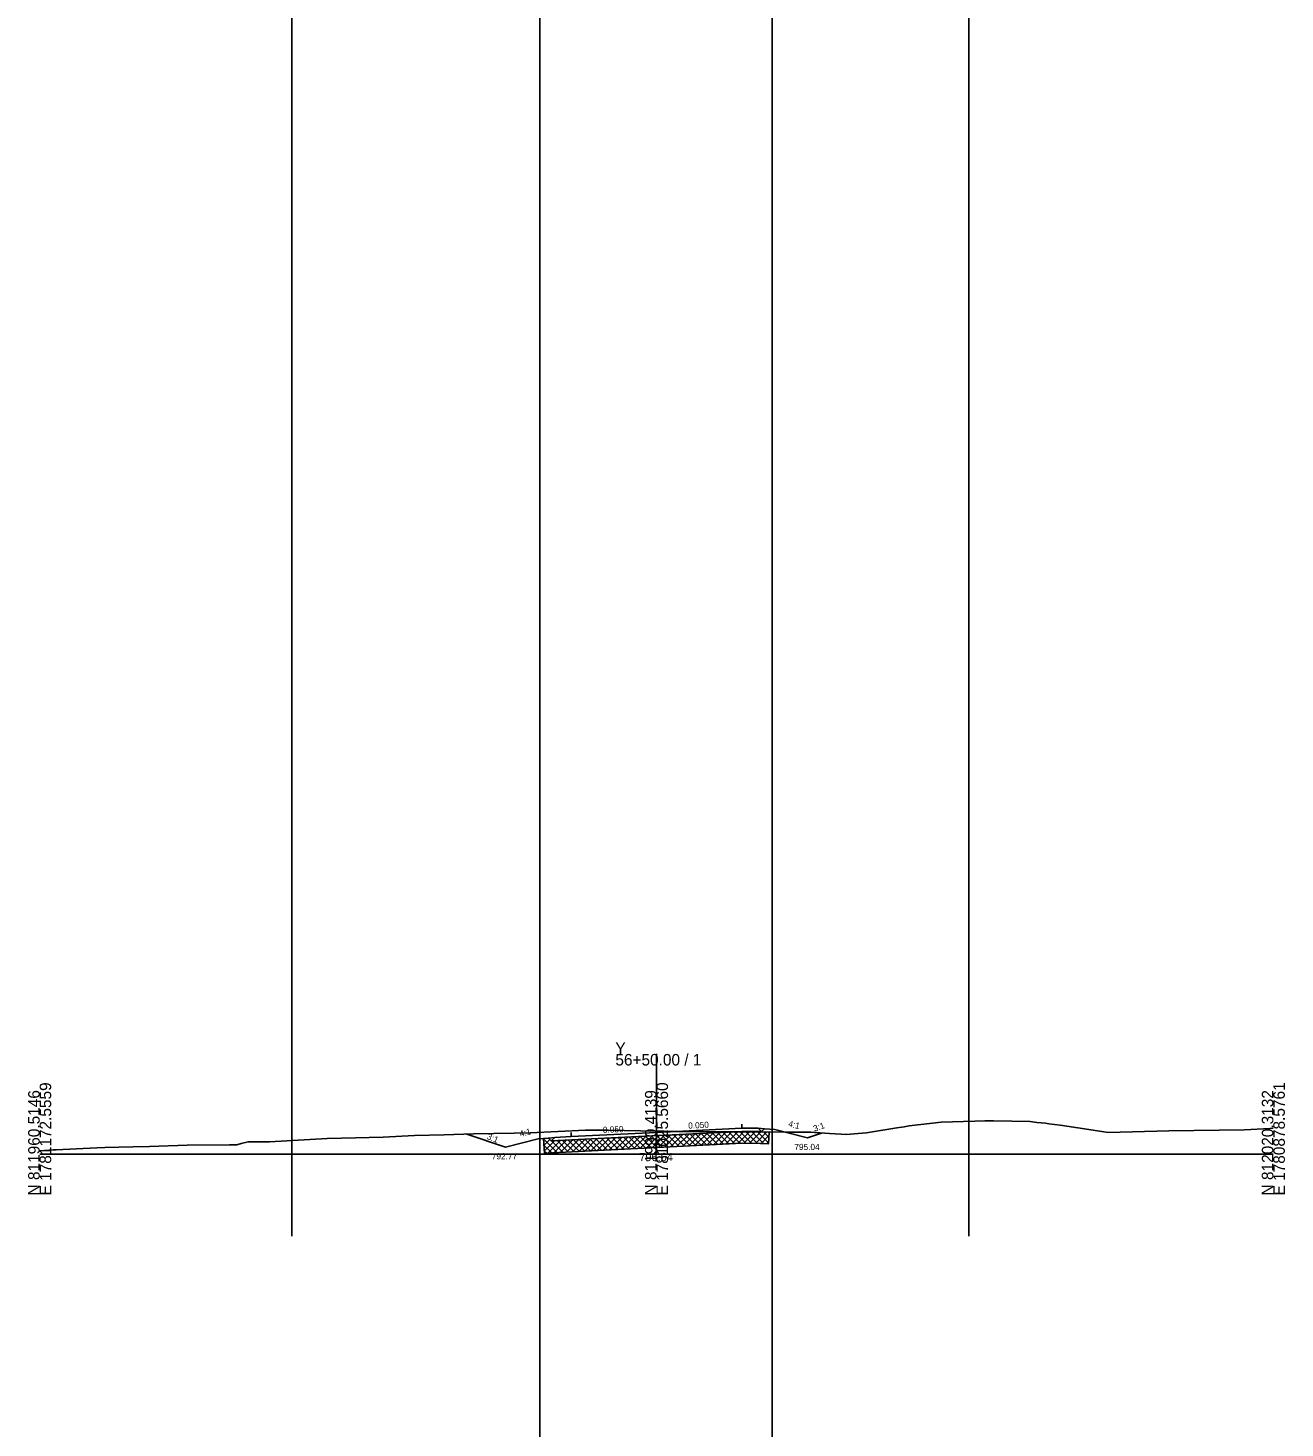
# Model space of a CAD drawing. Extents: x -12583 to 5303, y -44 to 25667.
# Drawn here: x 3997.2 to 4302.8, y 6933.5 to 7273.8 of the extents above; entities that cross this region are included whole.
import ezdxf

# ---------------------------------------------------------------- set-up
doc = ezdxf.new("R2010")
doc.units = 0
for name, color, linetype in [('Exist Cross Section Cell', 7, 'Continuous'), ('Exist XS Center Line Elevation Label', 7, 'Continuous'), ('Exist XS Ground Line', 7, 'Continuous'), ('Prop XS Ditch Slope Text', 7, 'Continuous'), ('Prop XS Ditch Standard Text', 7, 'Continuous'), ('Prop XS Dump Level', 7, 'Continuous'), ('Prop XS Earthwork Shape', 7, 'Continuous'), ('Prop XS Earthwork Undercut', 7, 'Continuous'), ('Prop XS EOT Tick Mark', 7, 'Continuous'), ('Prop XS Exc Vertical Line 1', 7, 'Continuous'), ('Prop XS Exc Vertical Line 2', 7, 'Continuous'), ('Prop XS Finish Grade', 7, 'Continuous'), ('Prop XS Finish Grade Earthwork', 7, 'Continuous'), ('Prop XS Finish Grade Paved Shoulder', 7, 'Continuous'), ('Prop XS Finish Grade Pavement', 7, 'Continuous'), ('Prop XS Pvmt Edge Slope', 7, 'Continuous'), ('Prop XS SE Text', 7, 'Continuous'), ('Prop XS Side Slope Text', 7, 'Continuous'), ('Prop XS Subgrade Earthwork', 7, 'Continuous'), ('Prop XS Undercut Exc Hatch', 7, 'Continuous'), ('Scratch_Level_1', 7, 'Continuous'), ('Scratch_Level_2', 7, 'Continuous'), ('Scratch_Level_3', 7, 'Continuous'), ('Scratch_Level_4', 7, 'Continuous'), ('Scratch_Level_6', 7, 'Continuous')]:
    doc.layers.add(name, color=color, linetype=linetype)

msp = doc.modelspace()

# ---------------------------------------------------------------- linework, layer by layer
at = {"layer": 'Exist Cross Section Cell'}
for p, q in [((4150, 7000), (4150, 7024.39)), ((4000, 7000), (4150, 7000)), ((4150, 7000), (4300, 7000))]:
    msp.add_line(p, q, dxfattribs=at)
at = {"layer": 'Exist XS Ground Line'}
for p, q in [((4211.47, 7006.89), (4219.25, 7007.79)), ((4219.25, 7007.79), (4227.42, 7008.06)), ((4227.42, 7008.06), (4229.86, 7008.13)), ((4229.86, 7008.13), (4231.93, 7008.1)), ((4231.93, 7008.1), (4240.89, 7007.98)), ((4240.89, 7007.98), (4242.49, 7007.75)), ((4083.51, 7004.14), (4091.12, 7004.57)), ((4091.12, 7004.57), (4098.37, 7004.7)), ((4098.37, 7004.7), (4105.5, 7004.94)), ((4105.5, 7004.94), (4115.39, 7005.14)), ((4115.39, 7005.14), (4119.29, 7005.26)), ((4119.29, 7005.26), (4132.74, 7005.86)), ((4132.74, 7005.86), (4134.88, 7005.87)), ((4134.88, 7005.87), (4138.25, 7005.85)), ((4138.25, 7005.85), (4150, 7005.64)), ((4150, 7005.64), (4151.89, 7005.6)), ((4151.89, 7005.6), (4170.92, 7005.45)), ((4170.92, 7005.45), (4172.83, 7005.47)), ((4172.83, 7005.47), (4174.69, 7005.44)), ((4174.69, 7005.44), (4187.56, 7005.36)), ((4187.56, 7005.36), (4192.08, 7005.03)), ((4192.08, 7005.03), (4196.25, 7004.79)), ((4196.25, 7004.79), (4198.05, 7004.98)), ((4198.05, 7004.98), (4201.03, 7005.25)), ((4201.03, 7005.25), (4208.45, 7006.44)), ((4208.45, 7006.44), (4210.21, 7006.71)), ((4210.21, 7006.71), (4211.47, 7006.89)), ((4242.49, 7007.75), (4244.61, 7007.58)), ((4244.61, 7007.58), (4245.41, 7007.39)), ((4245.41, 7007.39), (4248.19, 7007.07)), ((4248.19, 7007.07), (4254.08, 7006.18)), ((4254.08, 7006.18), (4259.86, 7005.32)), ((4259.86, 7005.32), (4274.61, 7005.68)), ((4274.61, 7005.68), (4292.97, 7005.94)), ((4292.97, 7005.94), (4299.16, 7006.29)), ((4299.16, 7006.29), (4300, 7006.33)), ((4000, 7000.81), (4003.29, 7001.05)), ((4003.29, 7001.05), (4004.04, 7001.09)), ((4004.04, 7001.09), (4013.86, 7001.6)), ((4013.86, 7001.6), (4015.85, 7001.66)), ((4015.85, 7001.66), (4022.63, 7001.82)), ((4022.63, 7001.82), (4026.69, 7001.93)), ((4026.69, 7001.93), (4035.83, 7002.26)), ((4035.83, 7002.26), (4046.17, 7002.33)), ((4046.17, 7002.33), (4047.92, 7002.34)), ((4047.92, 7002.34), (4048.96, 7002.64)), ((4048.96, 7002.64), (4050.67, 7003.03)), ((4050.67, 7003.03), (4055.92, 7003.04)), ((4055.92, 7003.04), (4065.67, 7003.57)), ((4065.67, 7003.57), (4069.92, 7003.86)), ((4069.92, 7003.86), (4073.39, 7003.95)), ((4073.39, 7003.95), (4083.51, 7004.14))]:
    msp.add_line(p, q, dxfattribs=at)
at = {"layer": 'Prop XS Dump Level'}
for p, q in [((4129.25, 7004.29), (4150, 7005.32)), ((4150, 7005.32), (4170.75, 7006.36))]:
    msp.add_line(p, q, dxfattribs=at)
at = {"layer": 'Prop XS Earthwork Shape'}
for points in [[(4138.25, 7005.85), (4150, 7005.64), (4151.89, 7005.6), (4168.78, 7005.47), (4147.16, 7004.39), (4129.29, 7003.49), (4124.42, 7003.25), (4123.7, 7003.96), (4121.25, 7003.77), (4113.25, 7001.77), (4103.89, 7004.89), (4105.5, 7004.94), (4115.39, 7005.14), (4119.29, 7005.26), (4132.74, 7005.86), (4134.88, 7005.87)], [(4172.83, 7005.47), (4174.69, 7005.44), (4181.32, 7005.4), (4178.75, 7006.04), (4176.24, 7006.22), (4175.55, 7005.52), (4170.77, 7005.57), (4168.78, 7005.47), (4170.92, 7005.45)], [(4181.32, 7005.4), (4186.75, 7004.04), (4190.14, 7005.17), (4187.56, 7005.36)]]:
    msp.add_lwpolyline(points, close=True, dxfattribs=at)
at = {"layer": 'Prop XS Earthwork Undercut'}
for p, q in [((4177.41, 7005.42), (4177.21, 7002.51)), ((4122.5, 7003.87), (4122.79, 7000.23)), ((4150.15, 7001.66), (4129.4, 7000.62)), ((4170.81, 7002.69), (4150.15, 7001.66)), ((4170.81, 7002.69), (4175.3, 7002.65)), ((4175.3, 7002.65), (4177.21, 7002.51)), ((4124.74, 7000.39), (4122.79, 7000.23)), ((4129.4, 7000.62), (4124.74, 7000.39))]:
    msp.add_line(p, q, dxfattribs=at)
at = {"layer": 'Prop XS EOT Tick Mark'}
for p, q in [((4129.25, 7004.29), (4129.25, 7005.29)), ((4170.75, 7006.36), (4170.75, 7007.36))]:
    msp.add_line(p, q, dxfattribs=at)
at = {"layer": 'Prop XS Exc Vertical Line 1'}
msp.add_line((4121.63, 6478.95), (4121.63, 9656.26), dxfattribs=at)
at = {"layer": 'Prop XS Exc Vertical Line 2'}
msp.add_line((4178.09, 6478.95), (4178.09, 9642.11), dxfattribs=at)
at = {"layer": 'Prop XS Finish Grade'}
for p, q in [((4174.75, 7006.32), (4176.24, 7006.22)), ((4125.25, 7004.09), (4123.7, 7003.96))]:
    msp.add_line(p, q, dxfattribs=at)
at = {"layer": 'Prop XS Finish Grade Earthwork'}
for p, q in [((4113.25, 7001.77), (4103.89, 7004.89)), ((4176.24, 7006.22), (4178.75, 7006.04)), ((4178.75, 7006.04), (4186.75, 7004.04)), ((4186.75, 7004.04), (4190.14, 7005.17)), ((4121.25, 7003.77), (4113.25, 7001.77)), ((4121.25, 7003.77), (4123.7, 7003.96))]:
    msp.add_line(p, q, dxfattribs=at)
at = {"layer": 'Prop XS Finish Grade Paved Shoulder'}
for p, q in [((4170.75, 7006.36), (4174.75, 7006.32)), ((4129.25, 7004.29), (4125.25, 7004.09))]:
    msp.add_line(p, q, dxfattribs=at)
at = {"layer": 'Prop XS Finish Grade Pavement'}
for p, q in [((4129.25, 7004.29), (4150, 7005.32)), ((4150, 7005.32), (4170.75, 7006.36))]:
    msp.add_line(p, q, dxfattribs=at)
at = {"layer": 'Prop XS Pvmt Edge Slope'}
for p, q in [((4174.75, 7006.32), (4175.55, 7005.52)), ((4125.25, 7004.09), (4124.42, 7003.25))]:
    msp.add_line(p, q, dxfattribs=at)
at = {"layer": 'Prop XS Subgrade Earthwork'}
for p, q in [((4129.29, 7003.49), (4147.16, 7004.39)), ((4147.16, 7004.39), (4170.77, 7005.57)), ((4170.77, 7005.57), (4175.55, 7005.52)), ((4175.55, 7005.52), (4176.24, 7006.22)), ((4124.42, 7003.25), (4123.7, 7003.96)), ((4129.29, 7003.49), (4124.42, 7003.25))]:
    msp.add_line(p, q, dxfattribs=at)
at = {"layer": 'Prop XS Undercut Exc Hatch'}
for p, q in [((4144.48, 7001.38), (4147.51, 7004.41)), ((4145.97, 7001.45), (4149, 7004.48)), ((4150, 7001.76), (4147.36, 7004.4)), ((4150, 7003.17), (4148.71, 7004.47)), ((4150, 7002.66), (4151.97, 7004.63)), ((4150, 7004.07), (4150.48, 7004.55)), ((4152.8, 7001.79), (4150.06, 7004.53)), ((4150.43, 7001.67), (4153.46, 7004.7)), ((4154.14, 7001.86), (4151.4, 7004.6)), ((4151.92, 7001.75), (4154.95, 7004.78)), ((4155.49, 7001.93), (4152.75, 7004.67)), ((4153.41, 7001.82), (4156.44, 7004.85)), ((4156.84, 7001.99), (4154.1, 7004.73)), ((4154.9, 7001.9), (4157.93, 7004.93)), ((4158.18, 7002.06), (4155.44, 7004.8)), ((4156.39, 7001.97), (4159.42, 7005)), ((4159.53, 7002.13), (4156.79, 7004.87)), ((4160, 7003.07), (4158.14, 7004.94)), ((4160, 7004.49), (4159.48, 7005)), ((4160, 7002.76), (4162.39, 7005.15)), ((4160, 7004.17), (4160.9, 7005.08)), ((4162.22, 7002.26), (4160, 7004.49)), ((4163.57, 7002.33), (4160.83, 7005.07)), ((4160.85, 7002.2), (4163.88, 7005.22)), ((4164.92, 7002.4), (4162.18, 7005.14)), ((4162.34, 7002.27), (4165.37, 7005.3)), ((4166.27, 7002.47), (4163.52, 7005.21)), ((4163.83, 7002.34), (4166.86, 7005.37)), ((4167.61, 7002.53), (4164.87, 7005.27)), ((4165.32, 7002.42), (4168.35, 7005.45)), ((4168.96, 7002.6), (4166.22, 7005.34)), ((4166.81, 7002.49), (4169.78, 7005.46)), ((4170, 7002.97), (4167.57, 7005.41)), ((4170, 7004.39), (4168.92, 7005.47)), ((4170, 7002.86), (4172.61, 7005.47)), ((4170, 7004.27), (4171.18, 7005.45)), ((4171.7, 7002.68), (4170, 7004.39)), ((4173.13, 7002.67), (4170.35, 7005.46)), ((4171.25, 7002.69), (4174.01, 7005.45)), ((4174.56, 7002.66), (4171.76, 7005.46)), ((4172.65, 7002.67), (4175.41, 7005.44)), ((4176.03, 7002.6), (4173.16, 7005.47)), ((4174.05, 7002.66), (4176.81, 7005.43)), ((4177.23, 7002.81), (4174.6, 7005.44)), ((4175.44, 7002.64), (4177.35, 7004.55)), ((4177.32, 7004.14), (4176.03, 7005.43)), ((4125.86, 7000.45), (4122.51, 7003.8)), ((4124.52, 7000.37), (4122.63, 7002.26)), ((4122.64, 7002.17), (4124.07, 7003.6)), ((4122.74, 7000.86), (4125.18, 7003.29)), ((4123.6, 7000.3), (4126.67, 7003.36)), ((4127.21, 7000.51), (4124.47, 7003.25)), ((4125.12, 7000.41), (4128.15, 7003.44)), ((4128.55, 7000.58), (4125.81, 7003.32)), ((4126.61, 7000.48), (4129.64, 7003.51)), ((4129.9, 7000.65), (4127.16, 7003.39)), ((4128.1, 7000.56), (4130, 7002.46)), ((4130, 7001.96), (4128.51, 7003.46)), ((4129.59, 7000.63), (4130, 7001.04)), ((4130, 7003.38), (4129.85, 7003.52)), ((4130, 7001.04), (4132.62, 7003.66)), ((4130, 7002.46), (4131.13, 7003.59)), ((4132.59, 7000.78), (4130, 7003.38)), ((4131.25, 7000.71), (4130, 7001.96)), ((4131.08, 7000.71), (4134.11, 7003.74)), ((4133.94, 7000.85), (4131.2, 7003.59)), ((4135.29, 7000.92), (4132.55, 7003.66)), ((4132.57, 7000.78), (4135.6, 7003.81)), ((4136.63, 7000.98), (4133.89, 7003.72)), ((4134.06, 7000.86), (4137.09, 7003.88)), ((4137.98, 7001.05), (4135.24, 7003.79)), ((4135.55, 7000.93), (4138.57, 7003.96)), ((4139.33, 7001.12), (4136.59, 7003.86)), ((4137.03, 7001), (4140, 7003.97)), ((4140, 7001.86), (4137.93, 7003.93)), ((4138.52, 7001.08), (4140, 7002.56)), ((4140, 7003.28), (4139.28, 7003.99)), ((4140, 7002.56), (4141.55, 7004.11)), ((4140, 7003.97), (4140.06, 7004.03)), ((4142.02, 7001.25), (4140, 7003.28)), ((4140.67, 7001.19), (4140, 7001.86)), ((4140.01, 7001.15), (4143.04, 7004.18)), ((4143.37, 7001.32), (4140.63, 7004.06)), ((4141.5, 7001.23), (4144.53, 7004.26)), ((4144.72, 7001.39), (4141.97, 7004.13)), ((4142.99, 7001.3), (4146.02, 7004.33)), ((4146.06, 7001.46), (4143.32, 7004.2)), ((4147.41, 7001.52), (4144.67, 7004.26)), ((4148.76, 7001.59), (4146.02, 7004.33)), ((4147.45, 7001.53), (4150, 7004.07)), ((4148.94, 7001.6), (4150, 7002.66)), ((4151.45, 7001.72), (4150, 7003.17)), ((4150.1, 7001.66), (4150, 7001.76)), ((4157.88, 7002.05), (4160, 7004.17)), ((4159.36, 7002.12), (4160, 7002.76)), ((4160.88, 7002.2), (4160, 7003.07)), ((4168.3, 7002.57), (4170, 7004.27)), ((4169.78, 7002.64), (4170, 7002.86)), ((4170.31, 7002.67), (4170, 7002.97)), ((4176.76, 7002.55), (4177.25, 7003.03)), ((4123.21, 7000.27), (4122.75, 7000.72))]:
    msp.add_line(p, q, dxfattribs=at)
at = {"layer": 'Scratch_Level_1'}
msp.add_line((4061.32, 9572.59), (4061.32, 6980.12), dxfattribs=at)
at = {"layer": 'Scratch_Level_2'}
msp.add_line((4225.92, 9572.59), (4225.92, 6980.12), dxfattribs=at)
at = {"layer": 'Scratch_Level_3'}
msp.add_lwpolyline([(4129.25, 7004.29), (4150, 7005.32), (4155.11, 7005.58), (4168.78, 7005.47), (4147.16, 7004.39), (4129.29, 7003.49), (4124.42, 7003.25), (4123.7, 7003.96), (4125.25, 7004.09)], close=True, dxfattribs=at)
at = {"layer": 'Scratch_Level_4'}
for points in [[(4103.89, 7004.89), (4105.5, 7004.94), (4115.39, 7005.14), (4119.29, 7005.26), (4132.74, 7005.86), (4134.88, 7005.87), (4138.25, 7005.85), (4150, 7005.64), (4151.89, 7005.6), (4168.78, 7005.47), (4147.16, 7004.39), (4129.29, 7003.49), (4124.42, 7003.25), (4123.7, 7003.96), (4121.25, 7003.77), (4113.25, 7001.77)], [(4181.32, 7005.4), (4187.56, 7005.36), (4190.14, 7005.17), (4186.75, 7004.04)]]:
    msp.add_lwpolyline(points, close=True, dxfattribs=at)
at = {"layer": 'Scratch_Level_6'}
msp.add_lwpolyline([(4122.5, 7003.87), (4123.7, 7003.96), (4124.42, 7003.25), (4129.29, 7003.49), (4147.16, 7004.39), (4168.78, 7005.47), (4170.92, 7005.45), (4172.83, 7005.47), (4174.69, 7005.44), (4177.41, 7005.42), (4177.21, 7002.51), (4175.3, 7002.65), (4170.81, 7002.69), (4150.15, 7001.66), (4129.4, 7000.62), (4124.74, 7000.39), (4122.79, 7000.23)], close=True, dxfattribs=at)
msp.add_lwpolyline([(4122.5, 7003.87), (4123.7, 7003.96), (4124.42, 7003.25), (4129.29, 7003.49), (4147.16, 7004.39), (4168.78, 7005.47), (4170.92, 7005.45), (4172.83, 7005.47), (4174.69, 7005.44), (4177.41, 7005.42), (4177.21, 7002.51), (4175.3, 7002.65), (4170.81, 7002.69), (4150.15, 7001.66), (4129.4, 7000.62), (4124.74, 7000.39), (4122.79, 7000.23)], close=True, dxfattribs=at)

# ---------------------------------------------------------------- texts
at = {"layer": 'Exist Cross Section Cell'}
for s, p in [('Y', (4140, 7024.39)), ('56+50.00 / 1', (4140, 7021.59))]:
    msp.add_text(s, height=2.8, dxfattribs=at).set_placement(p)
for s, p in [('N 811960.5146', (4000, 6990)), ('E 1781172.5559', (4002.8, 6990)), ('N 811990.4139', (4150, 6990)), ('E 1781025.5660', (4152.8, 6990)), ('N 812020.3132', (4300, 6990)), ('E 1780878.5761', (4302.8, 6990))]:
    msp.add_text(s, height=2.8, rotation=90, dxfattribs=at).set_placement(p)
at = {"layer": 'Exist XS Center Line Elevation Label'}
msp.add_text('796.64', height=2, dxfattribs=at).set_placement((4145.8, 6998.34))
at = {"layer": 'Prop XS Ditch Slope Text'}
for rotation, p in [(345.9638, (4181.94, 7006.79)), (14.0362, (4116.89, 7004.22))]:
    msp.add_text('4:1', height=1.5, rotation=rotation, dxfattribs=at).set_placement(p)
at = {"layer": 'Prop XS Ditch Standard Text'}
for s, p in [('795.04', (4183.53, 7001.04)), ('792.77', (4109.95, 6998.77))]:
    msp.add_text(s, height=1.5, dxfattribs=at).set_placement(p)
at = {"layer": 'Prop XS Dump Level'}
for p in [(4178.75, 7006), (4121.25, 7003.73)]:
    msp.add_text('Case2', height=0.04, dxfattribs=at).set_placement(p)
at = {"layer": 'Prop XS SE Text'}
for p in [(4157.75, 7006.21), (4137, 7005.17)]:
    msp.add_text('0.050', height=1.5, rotation=2.8624, dxfattribs=at).set_placement(p)
at = {"layer": 'Prop XS Side Slope Text'}
for rotation, p in [(338.2006, (4108.62, 7003.75)), (19.6191, (4188.43, 7005.48))]:
    msp.add_text('3:1', height=1.5, rotation=rotation, dxfattribs=at).set_placement(p)

doc.saveas('drawing.dxf')
